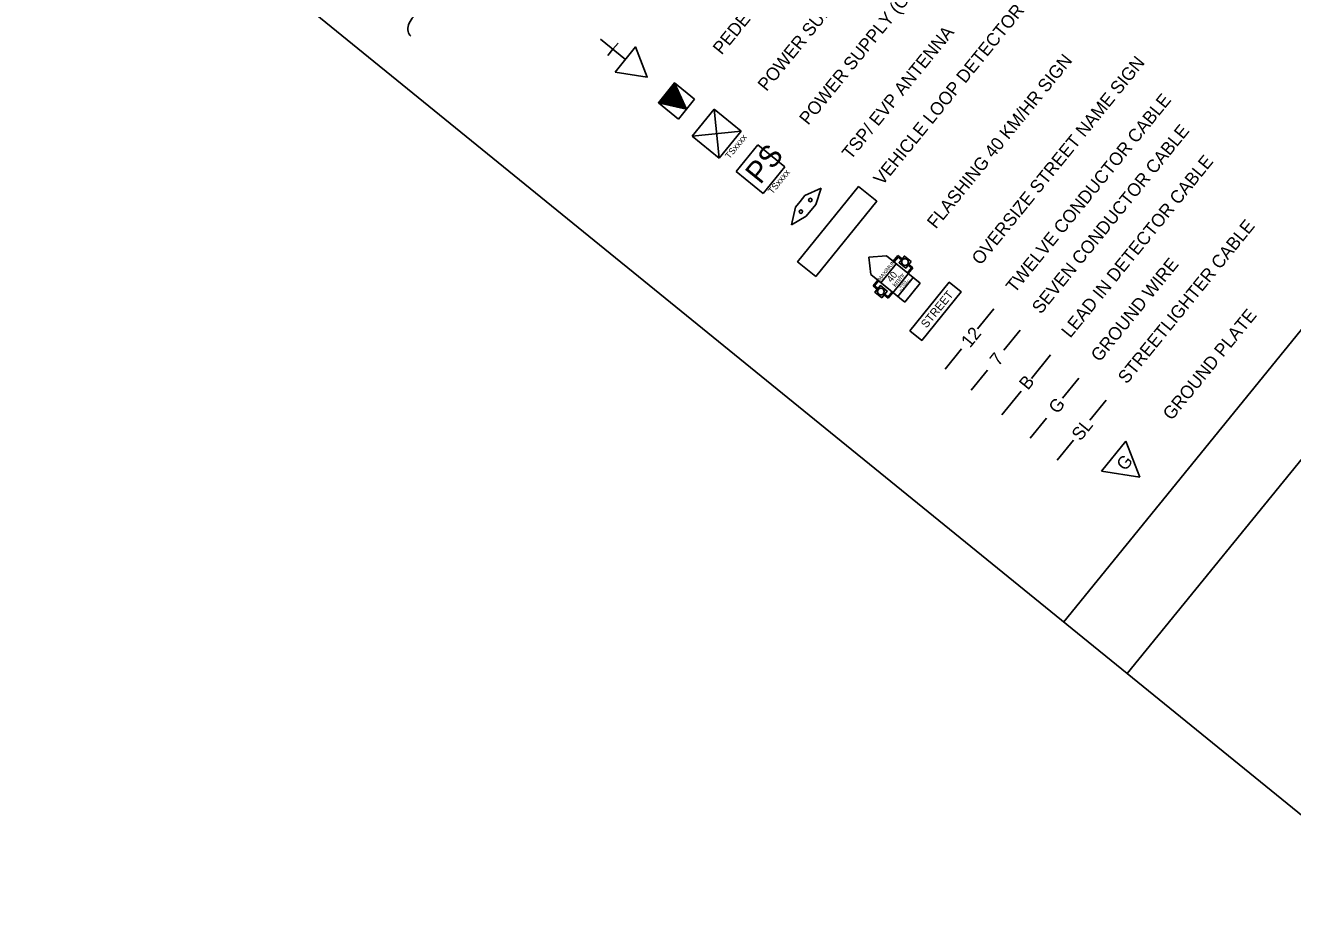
# Model space of a CAD drawing. Extents: x 592613 to 600223, y 4837996 to 4840103.
# Drawn here: x 592658.48 to 592701.09, y 4838932.93 to 4838962.54 of the extents above; entities that cross this region are included whole.
import ezdxf

# ---------------------------------------------------------------- set-up
doc = ezdxf.new("R2010")
doc.units = 0
for name, color, linetype in [('ENG_BORDER', 7, 'Continuous'), ('ENG_TITLEBLOCK', 7, 'Continuous'), ('TCS_LEGEND', 7, 'Continuous'), ('TCS_LOOP', 7, 'Continuous'), ('TCS_PLATE', 7, 'Continuous'), ('TCS_POWER', 7, 'Continuous'), ('TCS_SIGN', 7, 'Continuous'), ('TCS_SIGNALHEAD', 7, 'Continuous'), ('TCS_SPAN-EXIST', 7, 'Continuous'), ('TCS_TSP-EVP', 7, 'Continuous'), ('TCS_WR_12', 7, 'Continuous'), ('TCS_WR_7', 7, 'Continuous'), ('TCS_WR_B', 7, 'Continuous'), ('TCS_WR_G', 7, 'Continuous'), ('TCS_WR_SL', 7, 'Continuous')]:
    doc.layers.add(name, color=color, linetype=linetype)

msp = doc.modelspace()

# ---------------------------------------------------------------- linework, layer by layer
at = {"layer": 'ENG_BORDER'}
msp.add_lwpolyline([(592658.479, 4838970.843), (592762.862, 4838886.033)], dxfattribs=at)
at = {"layer": 'ENG_TITLEBLOCK'}
msp.add_line((592695.53, 4838940.74), (592723.069, 4838974.634), dxfattribs=at)
msp.add_line((592695.53, 4838940.74), (592723.069, 4838974.634), dxfattribs=at)
msp.add_lwpolyline([(592693.395, 4838942.474), (592720.934, 4838976.368)], dxfattribs=at)
at = {"layer": 'TCS_LOOP'}
msp.add_lwpolyline([(592685.052, 4838954.096), (592687.103, 4838956.621), (592686.497, 4838957.113), (592684.446, 4838954.589)], close=True, dxfattribs=at)
at = {"layer": 'TCS_PLATE'}
for p, q in [((592694.661, 4838947.546), (592695.482, 4838948.556)), ((592695.482, 4838948.556), (592695.946, 4838947.341)), ((592695.946, 4838947.341), (592694.661, 4838947.546))]:
    msp.add_line(p, q, dxfattribs=at)
at = {"layer": 'TCS_POWER'}
for p, q in [((592680.899, 4838958.812), (592681.638, 4838959.72)), ((592681.638, 4838959.72), (592682.547, 4838958.982)), ((592681.808, 4838958.073), (592681.638, 4838959.72)), ((592680.899, 4838958.812), (592682.547, 4838958.982)), ((592681.808, 4838958.073), (592680.899, 4838958.812)), ((592682.547, 4838958.982), (592681.808, 4838958.073)), ((592682.381, 4838957.618), (592683.109, 4838958.515)), ((592683.109, 4838958.515), (592684.016, 4838957.778)), ((592684.016, 4838957.778), (592683.287, 4838956.881)), ((592682.381, 4838957.618), (592683.288, 4838956.881))]:
    msp.add_line(p, q, dxfattribs=at)
at = {"layer": 'TCS_SIGN'}
for p, q in [((592686.844, 4838954.736), (592687.428, 4838954.79)), ((592687.428, 4838954.79), (592688.564, 4838953.868)), ((592687.815, 4838954.796), (592687.658, 4838954.603)), ((592687.958, 4838954.681), (592687.815, 4838954.796)), ((592686.911, 4838954.153), (592686.844, 4838954.736)), ((592687.243, 4838953.883), (592687.761, 4838954.52)), ((592687.821, 4838954.745), (592687.687, 4838954.58)), ((592687.935, 4838954.652), (592687.821, 4838954.745)), ((592688.274, 4838954.377), (592688.139, 4838954.212)), ((592688.159, 4838954.47), (592688.274, 4838954.377)), ((592688.324, 4838954.383), (592688.167, 4838954.189)), ((592688.182, 4838954.498), (592688.324, 4838954.383)), ((592686.911, 4838954.153), (592688.046, 4838953.23)), ((592686.984, 4838953.773), (592687.141, 4838953.966)), ((592687.035, 4838953.778), (592687.169, 4838953.943)), ((592687.648, 4838953.541), (592688.165, 4838954.178)), ((592687.809, 4838953.42), (592688.327, 4838954.057)), ((592687.126, 4838953.657), (592686.984, 4838953.773)), ((592687.149, 4838953.685), (592687.035, 4838953.778)), ((592687.373, 4838953.503), (592687.488, 4838953.41)), ((592687.488, 4838953.41), (592687.622, 4838953.575)), ((592687.493, 4838953.359), (592687.65, 4838953.552)), ((592688.046, 4838953.23), (592688.564, 4838953.868)), ((592687.351, 4838953.475), (592687.493, 4838953.359))]:
    msp.add_line(p, q, dxfattribs=at)
for points in [[(592688.262, 4838954.596), (592688.08, 4838954.372), (592687.855, 4838954.554), (592688.038, 4838954.779)], [(592687.271, 4838953.377), (592687.453, 4838953.601), (592687.229, 4838953.783), (592687.046, 4838953.559)], [(592688.215, 4838952.267), (592689.541, 4838953.9), (592689.945, 4838953.571), (592688.619, 4838951.939)]]:
    msp.add_lwpolyline(points, close=True, dxfattribs=at)
for centre in [(592688.056, 4838954.577), (592687.247, 4838953.582)]:
    msp.add_circle(centre, 0.111, dxfattribs=at)
at = {"layer": 'TCS_SIGNALHEAD'}
for p, q in [((592678.656, 4838961.388), (592677.812, 4838962.074)), ((592678.234, 4838961.731), (592678.063, 4838961.52)), ((592678.234, 4838961.731), (592678.406, 4838961.942)), ((592678.313, 4838960.966), (592678.999, 4838961.811)), ((592678.999, 4838961.811), (592679.387, 4838960.795)), ((592679.387, 4838960.795), (592678.313, 4838960.966)), ((592680.127, 4838959.849), (592680.079, 4838960.319)), ((592680.142, 4838959.846), (592680.092, 4838960.335)), ((592680.157, 4838959.843), (592680.104, 4838960.35)), ((592680.172, 4838959.84), (592680.117, 4838960.366)), ((592680.187, 4838959.836), (592680.13, 4838960.382)), ((592680.202, 4838959.833), (592680.143, 4838960.398)), ((592680.216, 4838959.83), (592680.156, 4838960.414)), ((592680.231, 4838959.826), (592680.169, 4838960.43)), ((592680.246, 4838959.823), (592680.182, 4838960.446)), ((592680.261, 4838959.82), (592680.195, 4838960.462)), ((592680.276, 4838959.816), (592680.208, 4838960.477)), ((592680.291, 4838959.813), (592680.22, 4838960.493)), ((592680.306, 4838959.81), (592680.233, 4838960.509)), ((592680.321, 4838959.806), (592680.246, 4838960.525)), ((592680.335, 4838959.803), (592680.259, 4838960.541)), ((592680.35, 4838959.8), (592680.272, 4838960.557)), ((592680.365, 4838959.797), (592680.285, 4838960.573)), ((592680.38, 4838959.793), (592680.298, 4838960.589)), ((592680.31, 4838960.604), (592680.983, 4838960.057)), ((592680.395, 4838959.79), (592680.311, 4838960.602)), ((592680.41, 4838959.787), (592680.33, 4838960.56)), ((592680.425, 4838959.783), (592680.349, 4838960.518)), ((592680.44, 4838959.78), (592680.368, 4838960.477)), ((592680.454, 4838959.777), (592680.386, 4838960.435)), ((592680.469, 4838959.773), (592680.405, 4838960.393)), ((592680.484, 4838959.77), (592680.424, 4838960.352)), ((592680.436, 4838959.383), (592679.763, 4838959.93)), ((592679.77, 4838959.929), (592679.769, 4838959.938)), ((592679.785, 4838959.926), (592679.782, 4838959.954)), ((592679.8, 4838959.922), (592679.795, 4838959.97)), ((592679.815, 4838959.919), (592679.808, 4838959.985)), ((592679.83, 4838959.916), (592679.821, 4838960.001)), ((592679.844, 4838959.912), (592679.834, 4838960.017)), ((592679.859, 4838959.909), (592679.847, 4838960.033)), ((592679.874, 4838959.906), (592679.859, 4838960.049)), ((592679.889, 4838959.902), (592679.872, 4838960.065)), ((592679.904, 4838959.899), (592679.885, 4838960.081)), ((592679.919, 4838959.896), (592679.898, 4838960.097)), ((592679.934, 4838959.892), (592679.911, 4838960.112)), ((592679.949, 4838959.889), (592679.924, 4838960.128)), ((592679.964, 4838959.886), (592679.937, 4838960.144)), ((592679.978, 4838959.883), (592679.95, 4838960.16)), ((592679.993, 4838959.879), (592679.963, 4838960.176)), ((592680.008, 4838959.876), (592679.975, 4838960.192)), ((592680.023, 4838959.873), (592679.988, 4838960.208)), ((592680.038, 4838959.869), (592680.001, 4838960.224)), ((592680.053, 4838959.866), (592680.014, 4838960.239)), ((592680.068, 4838959.863), (592680.027, 4838960.255)), ((592680.083, 4838959.859), (592680.04, 4838960.271)), ((592680.097, 4838959.856), (592680.053, 4838960.287)), ((592680.112, 4838959.853), (592680.066, 4838960.303)), ((592680.983, 4838960.057), (592680.436, 4838959.383)), ((592680.499, 4838959.767), (592680.443, 4838960.31)), ((592680.514, 4838959.764), (592680.462, 4838960.268)), ((592680.529, 4838959.76), (592680.481, 4838960.227)), ((592680.544, 4838959.757), (592680.499, 4838960.185)), ((592680.559, 4838959.754), (592680.518, 4838960.144)), ((592680.573, 4838959.75), (592680.537, 4838960.102)), ((592680.588, 4838959.747), (592680.556, 4838960.06)), ((592680.603, 4838959.744), (592680.575, 4838960.019)), ((592680.618, 4838959.74), (592680.594, 4838959.977)), ((592680.633, 4838959.737), (592680.612, 4838959.935)), ((592680.648, 4838959.734), (592680.631, 4838959.894)), ((592680.663, 4838959.73), (592680.65, 4838959.852)), ((592680.678, 4838959.727), (592680.669, 4838959.81)), ((592680.692, 4838959.724), (592680.688, 4838959.769)), ((592680.707, 4838959.721), (592680.707, 4838959.727))]:
    msp.add_line(p, q, dxfattribs=at)
for points in [[(592678.313, 4838960.966), (592678.999, 4838961.811), (592679.387, 4838960.795), (592679.387, 4838960.795)], [(592679.763, 4838959.93), (592680.31, 4838960.604), (592680.71, 4838959.72), (592680.71, 4838959.72)]]:
    msp.add_lwpolyline(points, close=True, dxfattribs=at)
at = {"layer": 'TCS_SPAN-EXIST'}
msp.add_ellipse((592671.757, 4838962.556), major_axis=(0.315, 0.388), ratio=0.7, start_param=0, end_param=3.141593, dxfattribs=at)
at = {"layer": 'TCS_TSP-EVP'}
for p, q in [((592684.691, 4838956.81), (592685.238, 4838957.064)), ((592685.055, 4838956.514), (592685.238, 4838957.064)), ((592684.373, 4838956.419), (592684.532, 4838956.615)), ((592684.532, 4838956.615), (592684.691, 4838956.81)), ((592684.738, 4838956.123), (592685.055, 4838956.514)), ((592684.373, 4838956.419), (592684.237, 4838955.832)), ((592684.738, 4838956.123), (592684.237, 4838955.832))]:
    msp.add_line(p, q, dxfattribs=at)
for centre in [(592684.873, 4838956.662), (592684.555, 4838956.271)]:
    msp.add_circle(centre, 0.0578, dxfattribs=at)
at = {"layer": 'TCS_WR_12'}
for p, q in [((592690.497, 4838952.327), (592691.044, 4838953)), ((592689.403, 4838950.98), (592689.95, 4838951.653))]:
    msp.add_line(p, q, dxfattribs=at)
at = {"layer": 'TCS_WR_7'}
for p, q in [((592691.376, 4838951.612), (592691.923, 4838952.286)), ((592690.282, 4838950.266), (592690.829, 4838950.939))]:
    msp.add_line(p, q, dxfattribs=at)
at = {"layer": 'TCS_WR_B'}
for p, q in [((592692.305, 4838950.663), (592692.947, 4838951.454)), ((592691.306, 4838949.434), (592691.961, 4838950.24))]:
    msp.add_line(p, q, dxfattribs=at)
at = {"layer": 'TCS_WR_G'}
for p, q in [((592693.356, 4838950.004), (592693.903, 4838950.677)), ((592692.262, 4838948.657), (592692.809, 4838949.33))]:
    msp.add_line(p, q, dxfattribs=at)
at = {"layer": 'TCS_WR_SL'}
for p, q in [((592694.268, 4838949.263), (592694.815, 4838949.936)), ((592693.174, 4838947.916), (592693.721, 4838948.59))]:
    msp.add_line(p, q, dxfattribs=at)

# ---------------------------------------------------------------- texts
at = {"layer": 'TCS_LEGEND'}
for s, p in [('PEDESTRIAN SIGNAL HEAD', (592681.892, 4838961.519)), ('POWER SUPPLY PEDESTAL', (592683.4, 4838960.294)), ('POWER SUPPLY (ON POLE)', (592684.798, 4838959.158)), ('VEHICLE LOOP DETECTOR', (592687.294, 4838957.13)), ('TSP/ EVP ANTENNA', (592686.233, 4838957.992)), ('FLASHING 40 KM/HR SIGN', (592689.093, 4838955.668)), ('OVERSIZE STREET NAME SIGN', (592690.595, 4838954.447)), ('TWELVE CONDUCTOR CABLE', (592691.746, 4838953.512)), ('SEVEN CONDUCTOR CABLE', (592692.621, 4838952.801)), ('LEAD IN DETECTOR CABLE', (592693.611, 4838951.997)), ('STREETLIGHTER CABLE', (592695.513, 4838950.452)), ('GROUND WIRE', (592694.601, 4838951.192)), ('GROUND PLATE', (592697.021, 4838949.226))]:
    msp.add_text(s, height=0.43374, rotation=50.9061, dxfattribs=at).set_placement(p)
at = {"layer": 'TCS_PLATE'}
msp.add_text('G', height=0.434, rotation=50.9061, dxfattribs=at).set_placement((592695.462, 4838947.526))
at = {"layer": 'TCS_POWER'}
for s, height, p in [('TSxxxx', 0.2169, (592682.155, 4838958.027)), ('PS', 0.7229, (592683.19, 4838957.159)), ('TSxxxx', 0.2169, (592683.601, 4838956.846))]:
    msp.add_text(s, height=height, rotation=50.9061, dxfattribs=at).set_placement(p)
at = {"layer": 'TCS_SIGN'}
for s, height, p in [('MAXIMUM', 0.1265, (592687.218, 4838953.934)), ('40', 0.2318, (592687.597, 4838953.875)), ('km/hr', 0.1511, (592687.73, 4838953.73)), ('WHEN ', 0.0703, (592687.904, 4838953.7)), ('FLASHING', 0.0703, (592687.929, 4838953.582)), ('STREET', 0.2773, (592688.779, 4838952.336))]:
    msp.add_text(s, height=height, rotation=50.9061, dxfattribs=at).set_placement(p)
at = {"layer": 'TCS_WR_12'}
msp.add_text('12', height=0.4337, rotation=50.9061, dxfattribs=at).set_placement((592690.241, 4838951.667))
at = {"layer": 'TCS_WR_7'}
msp.add_text('7', height=0.434, rotation=50.9061, dxfattribs=at).set_placement((592691.201, 4838951.053))
at = {"layer": 'TCS_WR_B'}
msp.add_text('B', height=0.434, rotation=50.9061, dxfattribs=at).set_placement((592692.189, 4838950.246))
at = {"layer": 'TCS_WR_G'}
msp.add_text('G', height=0.434, rotation=50.9061, dxfattribs=at).set_placement((592693.181, 4838949.444))
at = {"layer": 'TCS_WR_SL'}
msp.add_text('SL', height=0.4337, rotation=50.9061, dxfattribs=at).set_placement((592693.955, 4838948.535))

doc.saveas('drawing.dxf')
